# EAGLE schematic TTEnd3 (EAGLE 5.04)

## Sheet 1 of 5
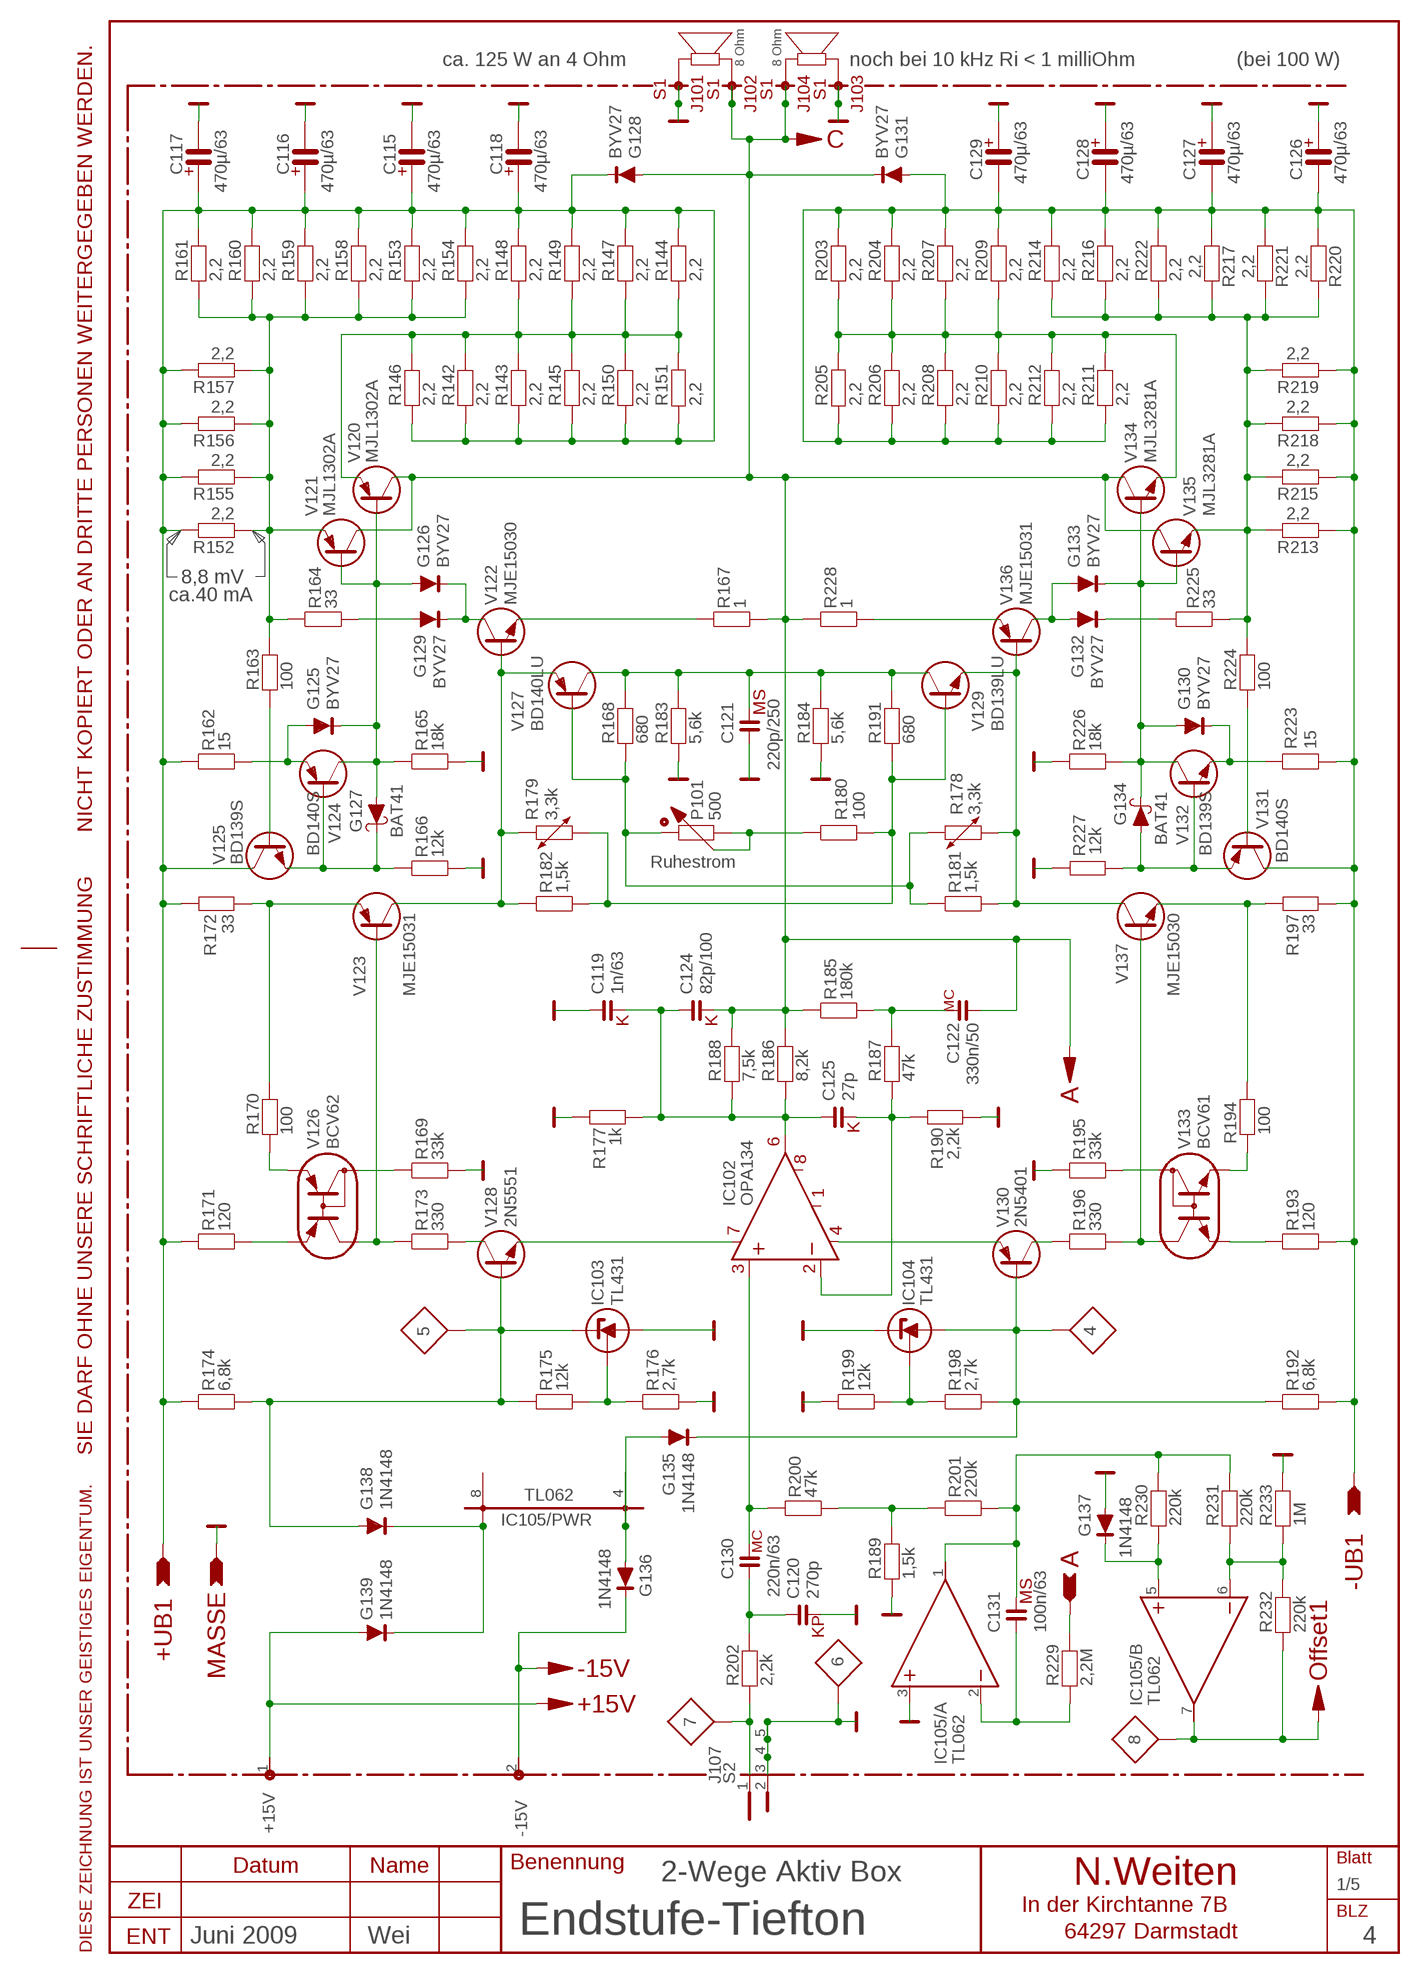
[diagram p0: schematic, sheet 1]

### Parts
C115  470µ/63  E05S12/LU  [E05S12,7U]
C116  470µ/63  E05S12/LU  [E05S12,7U]
C117  470µ/63  E05S12/LU  [E05S12,7U]
C118  470µ/63  E05S12/LU  [E05S12,7U]
C119  1n/63  K5S  [K5]
C120  270p  KP5/7/S  [KP5/7]
C121  220p/250  M05S4,5/L  [M05T4,5]
C122  330n/50  M05C4,5/S  [M05T4,5]
C124  82p/100  K5S  [K5]
C125  27p  K5S  [K5]
C126  470µ/63  E05S12/LU  [E05S12,7U]
C127  470µ/63  E05S12/LU  [E05S12,7U]
C128  470µ/63  E05S12/LU  [E05S12,7U]
C129  470µ/63  E05S12/LU  [E05S12,7U]
C130  220n/63  M05C4,5/L  [M05T4,5]
C131  100n/63  M05S2,5/L  [M05T2,5]
G125  BYV27  BYV27/S  [SOD-57]
G126  BYV27  BYV27/S  [SOD-57]
G127  BAT41  [DIO7-5]
G128  BYV27  BYV27/S  [SOD-57]
G129  BYV27  BYV27/S  [SOD-57]
G130  BYV27  BYV27/S  [SOD-57]
G131  BYV27  BYV27/S  [SOD-57]
G132  BYV27  BYV27/S  [SOD-57]
G133  BYV27  BYV27/S  [SOD-57]
G134  BAT41  [DIO7-5]
G135  1N4148  1N4148/S  [DIO7-5]
G136  1N4148  1N4148/L  [DIO7-5]
G137  1N4148  1N4148/L  [DIO7-5]
G138  1N4148  1N4148/S  [DIO7-5]
G139  1N4148  1N4148/S  [DIO7-5]
IC102  OPA134  LM6361N  [DIL-8]
IC103  TL431  [TO-92/BC]
IC104  TL431  [TO-92/BC]
IC105  TL062  LF353  [DIL-8]
J4  BERG02SW  [BERG02SW]
J101  FLACH6,3  [FLACH6,3]
J102  FLACH6,3  [FLACH6,3]
J103  FLACH6,3  [FLACH6,3]
J104  FLACH6,3  [FLACH6,3]
J107  SMB  SMBR665  [SMBR665]
MP7  7  MESS-R/S  [MESSPU/R]
MP11  5  MESS-R/S  [MESSPU/R]
MP12  4  MESS-R/S  [MESSPU/R]
MP13  6  MESS-R/L  [MESSPU/R]
MP15  8  MESS-R/S  [MESSPU/R]
P101  500  POT6,7/S  [T82P]
R142  2,2  R0207L7,5  [R7,5]
R143  2,2  R0207L7,5  [R7,5]
R144  2,2  R0207L7,5  [R7,5]
R145  2,2  R0207L7,5  [R7,5]
R146  2,2  R0207L7,5  [R7,5]
R147  2,2  R0207L7,5  [R7,5]
R148  2,2  R0207L7,5  [R7,5]
R149  2,2  R0207L7,5  [R7,5]
R150  2,2  R0207L7,5  [R7,5]
R151  2,2  R0207L7,5  [R7,5]
R152  2,2  R0207L7,5  [R7,5]
R153  2,2  R0207L7,5  [R7,5]
R154  2,2  R0207L7,5  [R7,5]
R155  2,2  R0207L7,5  [R7,5]
R156  2,2  R0207L7,5  [R7,5]
R157  2,2  R0207L7,5  [R7,5]
R158  2,2  R0207L7,5  [R7,5]
R159  2,2  R0207L7,5  [R7,5]
R160  2,2  R0207L7,5  [R7,5]
R161  2,2  R0207L7,5  [R7,5]
R162  15  R0207S7,5  [R7,5]
R163  100  R0204LR5  [R5]
R164  33  R0207S7,5  [R7,5]
R165  18k  R0207S7,5  [R7,5]
R166  12k  R0207S7,5  [R7,5]
R167  1  R0207S7,5  [R7,5]
R168  680  R0204LR5  [R5]
R169  33k  R0204SR5  [R5]
R170  100  R0204LR5  [R5]
R171  120  R0204SR5  [R5]
R172  33  R0204SR5  [R5]
R173  330  R0204SR5  [R5]
R174  6,8k  R0207S7,5  [R7,5]
R175  12k  R0204SR5  [R5]
R176  2,7k  R0204SR5  [R5]
R177  1k  R0204SR5  [R5]
R178  3,3k  NTC5,0/SB  [NTC5,0B]
R179  3,3k  NTC5,0/SB  [NTC5,0B]
R180  100  R0204SR5  [R5]
R181  1,5k  R0204SR5  [R5]
R182  1,5k  R0204SR5  [R5]
R183  5,6k  R0207L10  [R10]
R184  5,6k  R0207L10  [R10]
R185  180k  R0204SR5  [R5]
R186  8,2k  R0204LR5  [R5]
R187  47k  R0204LR5  [R5]
R188  7,5k  R0204LR5  [R5]
R189  1,5k  R0204LR5  [R5]
R190  2,2k  R0204SR5  [R5]
R191  680  R0204LR5  [R5]
R192  6,8k  R0207S7,5  [R7,5]
R193  120  R0204SR5  [R5]
R194  100  R0204LR5  [R5]
R195  33k  R0204SR5  [R5]
R196  330  R0204SR5  [R5]
R197  33  R0204SR5  [R5]
R198  2,7k  R0204SR5  [R5]
R199  12k  R0204SR5  [R5]
R200  47k  R0204SR5  [R5]
R201  220k  R0204SR5  [R5]
R202  2,2k  R0204LR5  [R5]
R203  2,2  R0207L7,5  [R7,5]
R204  2,2  R0207L7,5  [R7,5]
R205  2,2  R0207L7,5  [R7,5]
R206  2,2  R0207L7,5  [R7,5]
R207  2,2  R0207L7,5  [R7,5]
R208  2,2  R0207L7,5  [R7,5]
R209  2,2  R0207L7,5  [R7,5]
R210  2,2  R0207L7,5  [R7,5]
R211  2,2  R0207L7,5  [R7,5]
R212  2,2  R0207L7,5  [R7,5]
R213  2,2  R0207L7,5  [R7,5]
R214  2,2  R0207L7,5  [R7,5]
R215  2,2  R0207L7,5  [R7,5]
R216  2,2  R0207L7,5  [R7,5]
R217  2,2  R0207L7,5  [R7,5]
R218  2,2  R0207L7,5  [R7,5]
R219  2,2  R0207L7,5  [R7,5]
R220  2,2  R0207L7,5  [R7,5]
R221  2,2  R0207L7,5  [R7,5]
R222  2,2  R0207L7,5  [R7,5]
R223  15  R0207S7,5  [R7,5]
R224  100  R0204LR5  [R5]
R225  33  R0207S7,5  [R7,5]
R226  18k  R0207S7,5  [R7,5]
R227  12k  R0207S7,5  [R7,5]
R228  1  R0207S7,5  [R7,5]
R229  2,2M  R0204LR5  [R5]
R230  220k  R0204LR5  [R5]
R231  220k  R0204LR5  [R5]
R232  220k  R0204LR5  [R5]
R233  1M  R0204LR5  [R5]
V120  MJL1302A  MJL1302ALU  [TO-264/LU]
V121  MJL1302A  MJL1302ALU  [TO-264/LU]
V122  MJE15030  MJE15030LU  [TO-220/LU]
V123  MJE15031  MJE15031LU  [TO-220/LU]
V124  BD140S  [TO-126/S]
V125  BD139S  [TO-126/S]
V126  BCV62  [SOT143]
V127  BD140LU  [TO-126/LU]
V128  2N5551  [TO-92]
V129  BD139LU  [TO-126/LU]
V130  2N5401  [TO-92]
V131  BD140S  [TO-126/S]
V132  BD139S  [TO-126/S]
V133  BCV61  [SOT143]
V134  MJL3281A  MJL3281ALU  [TO-264/LU]
V135  MJL3281A  MJL3281ALU  [TO-264/LU]
V136  MJE15031  MJE15031LU  [TO-220/LU]
V137  MJE15030  MJE15030LU  [TO-220/LU]

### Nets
+UB1: C115.1 C116.1 C117.1 C118.1 G128.2(K) R142.1 R143.1 R144.2 R145.1 R146.1 R147.2 R148.2 R149.2 R150.1 R151.2 R152.2 R153.2 R154.2 R155.2 R156.2 R157.2 R158.2 R159.2 R160.2 R161.2 R162.1 R171.1 R172.1 R174.1 V125.2(C) ; also sheet 3
-UB1: C126.2 C127.2 C128.2 C129.2 G131.1(A) R192.2 R193.2 R197.2 R203.2 R204.2 R205.2 R206.1 R207.2 R208.1 R209.2 R210.1 R211.1 R212.1 R213.2 R214.2 R215.2 R216.2 R217.2 R218.2 R219.2 R220.2 R221.2 R222.2 R223.2 V131.2(C) ; also sheet 3
MASSE: C115.2 C116.2 C117.2 C118.2 C119.1 C120.2 C121.1 C126.1 C127.1 C128.1 C129.1 G137.1(A) IC103.2(A) IC104.3(K) IC105.3(/A:+IN) J101.1 J101.2 J103.1 J103.2 J107.2(MASSE) J107.3(MASSE) J107.4(MASSE) J107.5(MASSE) MP13.1 R165.2 R166.2 R169.2 R176.2 R177.1 R183.1 R184.1 R189.1 R190.2 R195.1 R199.1 R226.1 R227.1 R233.2 ; also sheet 2,3,4
N$1: C120.1 C130.1 R202.2
N$2: C130.2 IC102.3(+IN) R200.1
N$3: IC103.1(R) R175.2 R176.1
N$4: G138.1(A) IC103.3(K) MP11.1 R174.2 R175.1 V128.2(B)
N$5: IC102.7(V+) V128.1(E)
N$6: IC104.1(R) R198.1 R199.2
N$7: G135.2(K) IC104.2(A) MP12.1 R192.1 R198.2 V130.2(B)
N$8: IC102.4(V-) V130.1(E)
N$9: C119.2 C124.1 C125.1 IC102.6(OUT) R177.2 R186.1 R188.1
N$10: C125.2 IC102.2(-IN) R187.1 R190.1
N$11: C122.2 R185.2 R187.2
N$13: R173.2 V128.3(C)
N$14: R196.1 V130.3(C)
N$15: R170.2 R172.2 V123.3(E)
N$16: C121.2 R168.2 R183.2 R184.2 R191.2 V127.2(C) V129.2(C)
N$17: R171.2 V126.3(E1)
N$18: R178.2 R181.2 V129.1(E) V136.1(B) V137.2(C)
N$19: R173.1 V123.1(B) V126.2(C1)
N$20: R169.1 V126.1(B1B2C2)
N$21: R170.1 V126.4(E2)
N$22: R193.1 V133.3(E1)
N$23: G125.2(K) G126.1(A) G127.1(A) R165.1 V120.1(B) V121.1(B) V124.2(C)
N$24: G125.1(A) R162.2 V124.1(E)
N$25: J107.1 MP7.1 R202.1
N$26: R152.1 R153.1 R154.1 R155.1 R156.1 R157.1 R158.1 R159.1 R160.1 R161.1 R163.2 R164.1 V121.3(E)
N$27: R196.2 V133.2(C1) V137.1(B)
N$28: R195.2 V133.1(B1B2C2)
N$30: R194.1 V133.4(E2)
N$31: R194.2 R197.1 V137.3(E)
N$32: R163.1 V125.3(B)
N$33: G127.2(K) R166.1 V124.3(B) V125.1(E)
N$35: R213.1 R214.1 R215.1 R216.1 R217.1 R218.1 R219.1 R220.1 R221.1 R222.1 R224.2 R225.2 V135.3(E)
N$36: G130.2(K) R223.1 V132.1(E)
N$37: G130.1(A) G133.2(K) G134.2(K) R226.2 V132.2(C) V134.1(B) V135.1(B)
N$38: G132.1(A) G133.1(A) V136.2(C)
N$39: G132.2(K) R225.1
N$40: R224.1 V131.3(B)
N$41: G134.1(A) R227.2 V131.1(E) V132.3(B)
N$42: R167.1 V122.3(E)
N$43: C131.2 IC105.1(/A:OUT) R201.2 R230.2 R231.2
N$44: C131.1 IC105.2(/A:-IN) R229.1
N$45: G137.2(K) IC105.5(/B:+IN) R230.1
N$46: IC105.6(/B:-IN) R231.1 R232.2 R233.1
N$47: G135.1(A) G136.1(A) IC105.4(/PWR:VEE)
N$50: R142.2 R143.2 R144.1 R145.2 R146.2 R147.1 R148.1 R149.1 R150.2 R151.1 V120.3(E)
N$51: R203.1 R204.1 R205.1 R206.2 R207.1 R208.2 R209.1 R210.2 R211.2 R212.2 V134.3(E)
N$52: C122.1 C124.2 G128.1(A) G131.2(K) J102.1 J102.2 J104.1 J104.2 R167.2 R185.1 R186.2 R188.2 R228.1 R229.2 V120.2(C) V121.2(C) V134.2(C) V135.2(C) ; also sheet 3
N$93: R189.2 R200.2 R201.1
N$98: G136.2(K) J4.2 ; also sheet 2
N$187: R179.1 R182.1 V122.1(B) V123.2(C) V127.1(E)
N$204: P101.1 R168.1 R178.1 R181.1 V127.3(B)
N$205: R179.2 R180.2 R182.2 R191.1 V129.3(B)
N$214: G138.2(K) G139.2(K) IC105.8(/PWR:VCC)
N$215: G139.1(A) J4.1 ; also sheet 2
N$218: P101.2 P101.S R180.1
N$219: R228.2 V136.3(E)
N$220: G126.2(K) G129.2(K) V122.2(C)
N$221: G129.1(A) R164.2
OFFSET1: IC105.7(/B:OUT) MP15.1 R232.1 ; also sheet 3
Unconnected: IC102.1(BAL1) IC102.8(BAL2)

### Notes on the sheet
- ca. 125 W an 4 Ohm | 8 Ohm | 8 Ohm | noch bei 10 kHz Ri < 1 milliOhm | (bei 100 W)
- 8,8 mV
- ca.40 mA
- Ruhestrom
- +15V | -15V
- 2-Wege Aktiv Box
- Endstufe-Tiefton
- Juni 2009 | Wei | 4

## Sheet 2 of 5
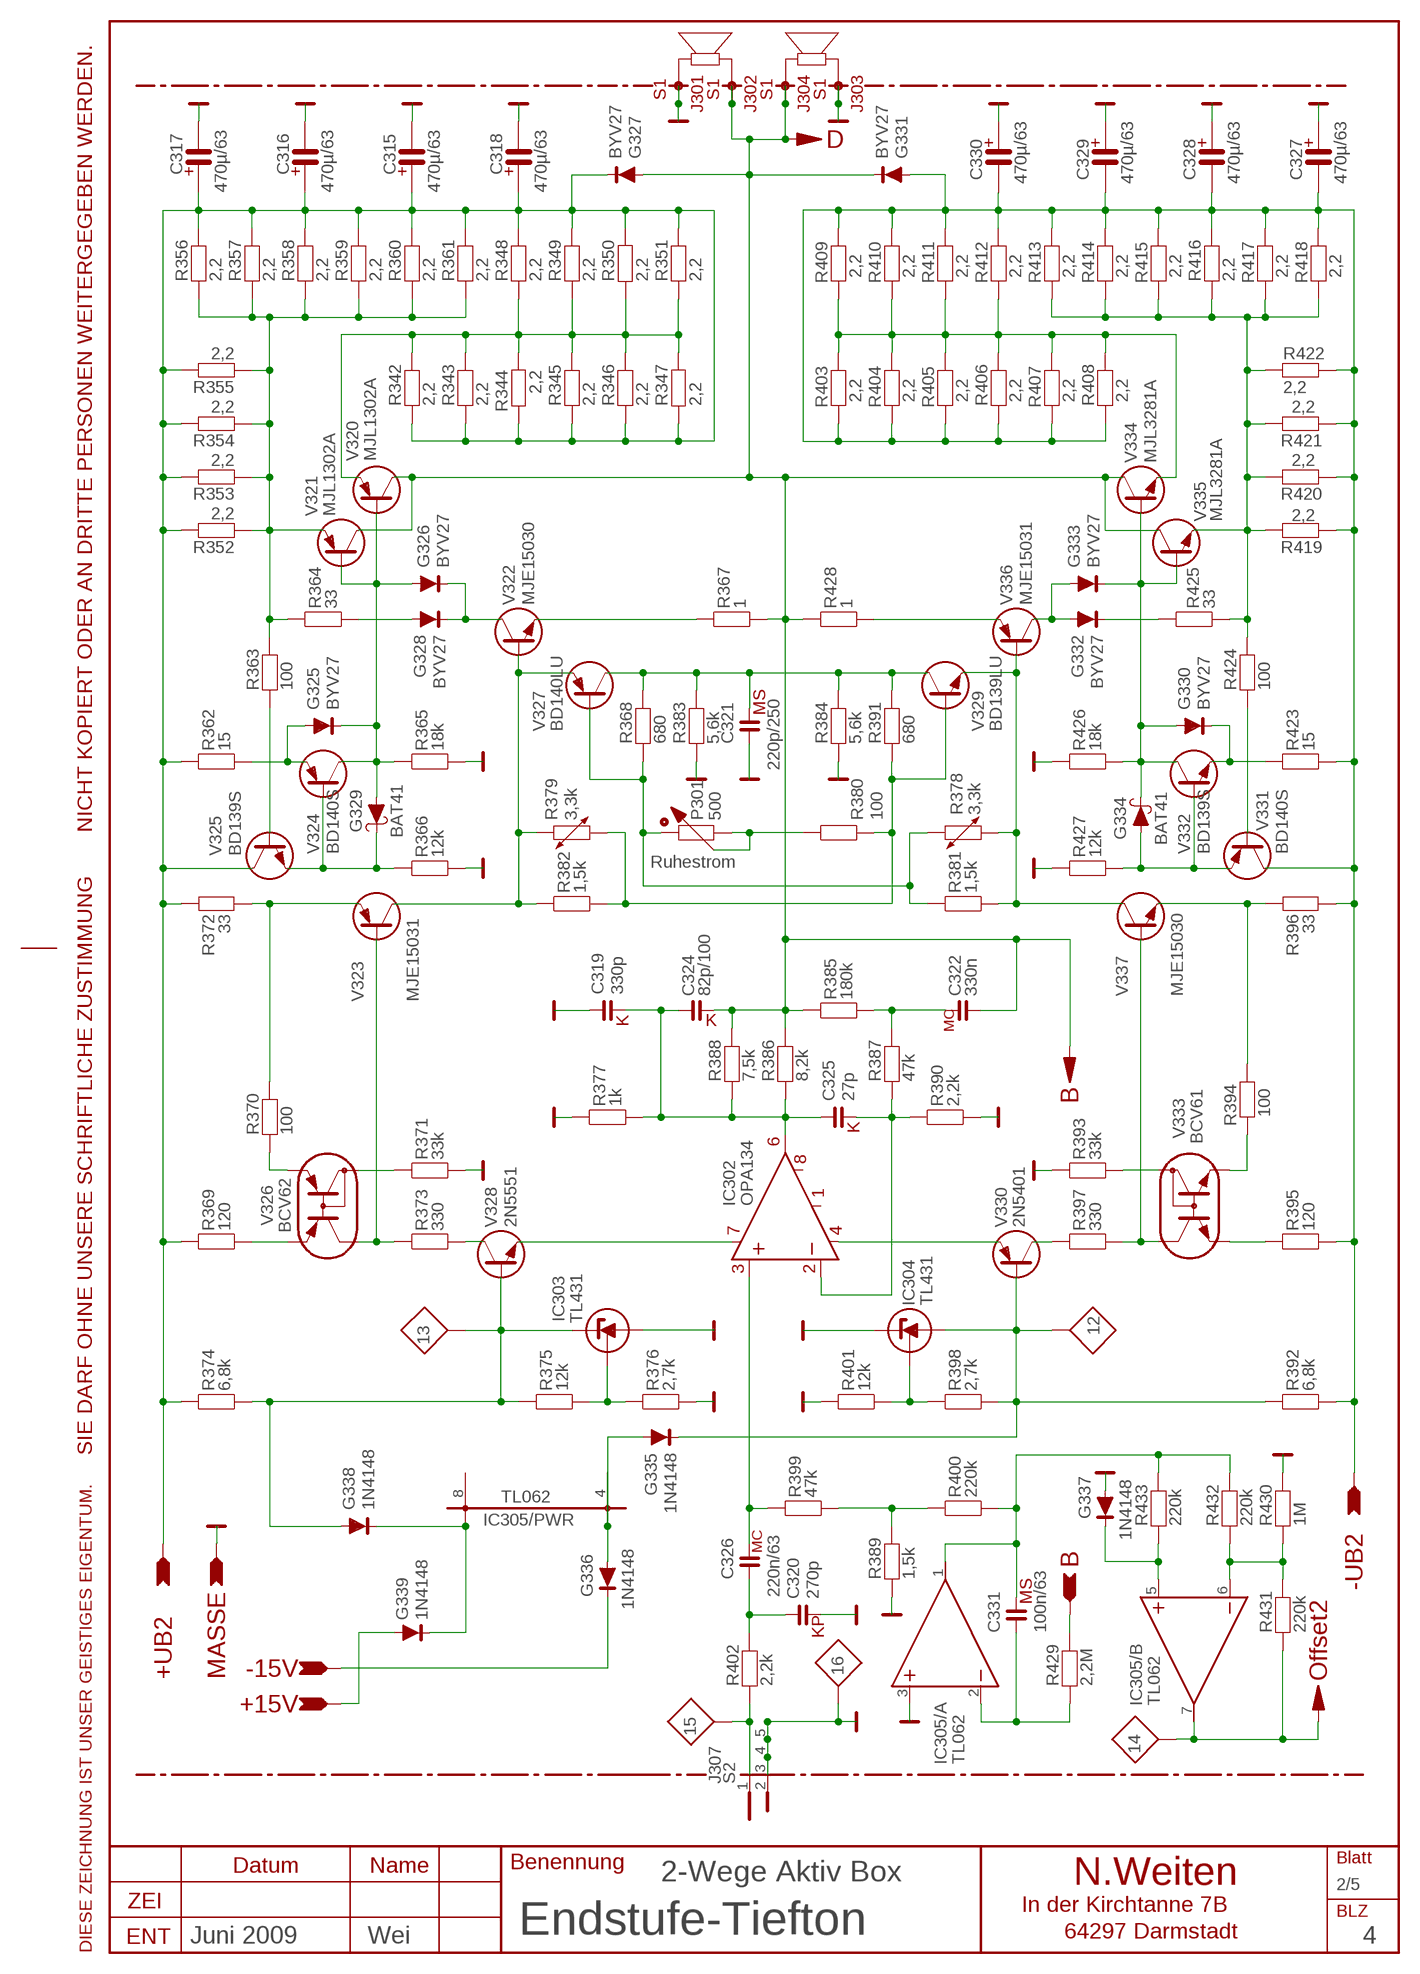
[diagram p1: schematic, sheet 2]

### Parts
C315  470µ/63  E05S12/LU  [E05S12,7U]
C316  470µ/63  E05S12/LU  [E05S12,7U]
C317  470µ/63  E05S12/LU  [E05S12,7U]
C318  470µ/63  E05S12/LU  [E05S12,7U]
C319  330p  K5S  [K5]
C320  270p  KP5/7/S  [KP5/7]
C321  220p/250  M05S4,5/L  [M05T4,5]
C322  330n  M05C4,5/S  [M05T4,5]
C324  82p/100  K5L  [K5]
C325  27p  K5S  [K5]
C326  220n/63  M05C4,5/L  [M05T4,5]
C327  470µ/63  E05S12/LU  [E05S12,7U]
C328  470µ/63  E05S12/LU  [E05S12,7U]
C329  470µ/63  E05S12/LU  [E05S12,7U]
C330  470µ/63  E05S12/LU  [E05S12,7U]
C331  100n/63  M05S2,5/L  [M05T2,5]
G325  BYV27  BYV27/S  [SOD-57]
G326  BYV27  BYV27/S  [SOD-57]
G327  BYV27  BYV27/S  [SOD-57]
G328  BYV27  BYV27/S  [SOD-57]
G329  BAT41  [DIO7-5]
G330  BYV27  BYV27/S  [SOD-57]
G331  BYV27  BYV27/S  [SOD-57]
G332  BYV27  BYV27/S  [SOD-57]
G333  BYV27  BYV27/S  [SOD-57]
G334  BAT41  [DIO7-5]
G335  1N4148  1N4148/S  [DIO7-5]
G336  1N4148  1N4148/L  [DIO7-5]
G337  1N4148  1N4148/L  [DIO7-5]
G338  1N4148  1N4148/S  [DIO7-5]
G339  1N4148  1N4148/S  [DIO7-5]
IC302  OPA134  LM6361N  [DIL-8]
IC303  TL431  [TO-92/BC]
IC304  TL431  [TO-92/BC]
IC305  TL062  LF353  [DIL-8]
J301  FLACH6,3  [FLACH6,3]
J302  FLACH6,3  [FLACH6,3]
J303  FLACH6,3  [FLACH6,3]
J304  FLACH6,3  [FLACH6,3]
J307  SMB  SMBR665  [SMBR665]
MP8  15  MESS-R/S  [MESSPU/R]
MP9  13  MESS-R/S  [MESSPU/R]
MP10  12  MESS-R/S  [MESSPU/R]
MP14  16  MESS-R/L  [MESSPU/R]
MP16  14  MESS-R/S  [MESSPU/R]
P301  500  POT6,7/S  [T82P]
R342  2,2  R0207L7,5  [R7,5]
R343  2,2  R0207L7,5  [R7,5]
R344  2,2  R0207L7,5  [R7,5]
R345  2,2  R0207L7,5  [R7,5]
R346  2,2  R0207L7,5  [R7,5]
R347  2,2  R0207L7,5  [R7,5]
R348  2,2  R0207L7,5  [R7,5]
R349  2,2  R0207L7,5  [R7,5]
R350  2,2  R0207L7,5  [R7,5]
R351  2,2  R0207L7,5  [R7,5]
R352  2,2  R0207L7,5  [R7,5]
R353  2,2  R0207L7,5  [R7,5]
R354  2,2  R0207L7,5  [R7,5]
R355  2,2  R0207L7,5  [R7,5]
R356  2,2  R0207L7,5  [R7,5]
R357  2,2  R0207L7,5  [R7,5]
R358  2,2  R0207L7,5  [R7,5]
R359  2,2  R0207L7,5  [R7,5]
R360  2,2  R0207L7,5  [R7,5]
R361  2,2  R0207L7,5  [R7,5]
R362  15  R0207S7,5  [R7,5]
R363  100  R0204LR5  [R5]
R364  33  R0207S7,5  [R7,5]
R365  18k  R0207S7,5  [R7,5]
R366  12k  R0207S7,5  [R7,5]
R367  1  R0207S7,5  [R7,5]
R368  680  R0204LR5  [R5]
R369  120  R0204SR5  [R5]
R370  100  R0204LR5  [R5]
R371  33k  R0204SR5  [R5]
R372  33  R0204SR5  [R5]
R373  330  R0204SR5  [R5]
R374  6,8k  R0207S7,5  [R7,5]
R375  12k  R0204SR5  [R5]
R376  2,7k  R0204SR5  [R5]
R377  1k  R0204SR5  [R5]
R378  3,3k  NTC5,0/SB  [NTC5,0B]
R379  3,3k  NTC5,0/SB  [NTC5,0B]
R380  100  R0204SR5  [R5]
R381  1,5k  R0204SR5  [R5]
R382  1,5k  R0204SR5  [R5]
R383  5,6k  R0207L10  [R10]
R384  5,6k  R0207L10  [R10]
R385  180k  R0204SR5  [R5]
R386  8,2k  R0204LR5  [R5]
R387  47k  R0204LR5  [R5]
R388  7,5k  R0204LR5  [R5]
R389  1,5k  R0204LR5  [R5]
R390  2,2k  R0204SR5  [R5]
R391  680  R0204LR5  [R5]
R392  6,8k  R0207S7,5  [R7,5]
R393  33k  R0204SR5  [R5]
R394  100  R0204LR5  [R5]
R395  120  R0204SR5  [R5]
R396  33  R0204SR5  [R5]
R397  330  R0204SR5  [R5]
R398  2,7k  R0204SR5  [R5]
R399  47k  R0204SR5  [R5]
R400  220k  R0204SR5  [R5]
R401  12k  R0204SR5  [R5]
R402  2,2k  R0204LR5  [R5]
R403  2,2  R0207L7,5  [R7,5]
R404  2,2  R0207L7,5  [R7,5]
R405  2,2  R0207L7,5  [R7,5]
R406  2,2  R0207L7,5  [R7,5]
R407  2,2  R0207L7,5  [R7,5]
R408  2,2  R0207L7,5  [R7,5]
R409  2,2  R0207L7,5  [R7,5]
R410  2,2  R0207L7,5  [R7,5]
R411  2,2  R0207L7,5  [R7,5]
R412  2,2  R0207L7,5  [R7,5]
R413  2,2  R0207L7,5  [R7,5]
R414  2,2  R0207L7,5  [R7,5]
R415  2,2  R0207L7,5  [R7,5]
R416  2,2  R0207L7,5  [R7,5]
R417  2,2  R0207L7,5  [R7,5]
R418  2,2  R0207L7,5  [R7,5]
R419  2,2  R0207L7,5  [R7,5]
R420  2,2  R0207L7,5  [R7,5]
R421  2,2  R0207L7,5  [R7,5]
R422  2,2  R0207L7,5  [R7,5]
R423  15  R0207S7,5  [R7,5]
R424  100  R0204LR5  [R5]
R425  33  R0207S7,5  [R7,5]
R426  18k  R0207S7,5  [R7,5]
R427  12k  R0207S7,5  [R7,5]
R428  1  R0207S7,5  [R7,5]
R429  2,2M  R0204LR5  [R5]
R430  1M  R0204LR5  [R5]
R431  220k  R0204LR5  [R5]
R432  220k  R0204LR5  [R5]
R433  220k  R0204LR5  [R5]
V320  MJL1302A  MJL1302ALU  [TO-264/LU]
V321  MJL1302A  MJL1302ALU  [TO-264/LU]
V322  MJE15030  MJE15030LU  [TO-220/LU]
V323  MJE15031  MJE15031LU  [TO-220/LU]
V324  BD140S  [TO-126/S]
V325  BD139S  [TO-126/S]
V326  BCV62  [SOT143]
V327  BD140LU  [TO-126/LU]
V328  2N5551  [TO-92]
V329  BD139LU  [TO-126/LU]
V330  2N5401  [TO-92]
V331  BD140S  [TO-126/S]
V332  BD139S  [TO-126/S]
V333  BCV61  [SOT143]
V334  MJL3281A  MJL3281ALU  [TO-264/LU]
V335  MJL3281A  MJL3281ALU  [TO-264/LU]
V336  MJE15031  MJE15031LU  [TO-220/LU]
V337  MJE15030  MJE15030LU  [TO-220/LU]

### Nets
+UB2: C315.1 C316.1 C317.1 C318.1 G327.2(K) R342.1 R343.1 R344.2 R345.1 R346.1 R347.2 R348.2 R349.2 R350.1 R351.2 R352.2 R353.2 R354.2 R355.2 R356.2 R357.2 R358.2 R359.2 R360.2 R361.2 R362.1 R369.1 R372.1 R374.1 V325.2(C) ; also sheet 4
-UB2: C327.2 C328.2 C329.2 C330.2 G331.1(A) R392.2 R395.2 R396.2 R403.2 R404.2 R405.2 R406.1 R407.2 R408.1 R409.2 R410.1 R411.1 R412.1 R413.2 R414.2 R415.2 R416.2 R417.2 R418.2 R419.2 R420.2 R421.2 R422.2 R423.2 V331.2(C) ; also sheet 4
MASSE: C315.2 C316.2 C317.2 C318.2 C319.1 C320.2 C321.1 C327.1 C328.1 C329.1 C330.1 G337.1(A) IC303.2(A) IC304.3(K) IC305.3(/A:+IN) J301.1 J301.2 J303.1 J303.2 J307.2(MASSE) J307.3(MASSE) J307.4(MASSE) J307.5(MASSE) MP14.1 R365.2 R366.2 R371.2 R376.2 R377.1 R383.1 R384.1 R389.1 R390.2 R393.1 R401.1 R426.1 R427.1 R430.2 ; also sheet 1,3,4
N$54: C326.2 IC302.3(+IN) R399.1
N$55: IC303.1(R) R375.2 R376.1
N$56: G338.1(A) IC303.3(K) MP9.1 R374.2 R375.1 V328.2(B)
N$58: IC304.1(R) R398.1 R401.2
N$59: IC302.4(V-) V330.1(E)
N$60: C319.2 C324.1 C325.1 IC302.6(OUT) R377.2 R386.1 R388.1
N$61: C325.2 IC302.2(-IN) R387.1 R390.1
N$62: C322.2 R385.2 R387.2
N$63: R373.2 V328.3(C)
N$64: R397.1 V330.3(C)
N$65: R370.2 R372.2 V323.3(E)
N$66: R379.1 R382.1 V322.1(B) V323.2(C) V327.1(E)
N$67: R369.2 V326.3(E1)
N$68: R373.1 V323.1(B) V326.2(C1)
N$69: R371.1 V326.1(B1B2C2)
N$70: R370.1 V326.4(E2)
N$72: IC302.7(V+) V328.1(E)
N$73: G325.1(A) R362.2 V324.1(E)
N$74: R352.1 R353.1 R354.1 R355.1 R356.1 R357.1 R358.1 R359.1 R360.1 R361.1 R363.2 R364.1 V321.3(E)
N$75: R397.2 V333.2(C1) V337.1(B)
N$76: R393.2 V333.1(B1B2C2)
N$77: R395.1 V333.3(E1)
N$78: R394.1 V333.4(E2)
N$79: R394.2 R396.1 V337.3(E)
N$80: R378.2 R381.2 V329.1(E) V336.1(B) V337.2(C)
N$82: R413.1 R414.1 R415.1 R416.1 R417.1 R418.1 R419.1 R420.1 R421.1 R422.1 R424.2 R425.2 V335.3(E)
N$83: G330.2(K) R423.1 V332.1(E)
N$84: G330.1(A) G333.2(K) G334.2(K) R426.2 V332.2(C) V334.1(B) V335.1(B)
N$85: J307.1 MP8.1 R402.1
N$86: R363.1 V325.3(B)
N$87: P301.1 R368.1 R378.1 R381.1 V327.3(B)
N$88: R379.2 R380.2 R382.2 R391.1 V329.3(B)
N$89: G335.2(K) IC304.2(A) MP10.1 R392.1 R398.2 V330.2(B)
N$90: C321.2 R368.2 R383.2 R384.2 R391.2 V327.2(C) V329.2(C)
N$91: G329.2(K) R366.1 V324.3(B) V325.1(E)
N$92: G328.1(A) R364.2
N$94: C331.2 IC305.1(/A:OUT) R400.2 R432.2 R433.2
N$95: C331.1 IC305.2(/A:-IN) R429.1
N$96: G337.2(K) IC305.5(/B:+IN) R433.1
N$97: IC305.6(/B:-IN) R430.1 R431.2 R432.1
N$98: G336.2(K) ; also sheet 1
N$101: R342.2 R343.2 R344.1 R345.2 R346.2 R347.1 R348.1 R349.1 R350.2 R351.1 V320.3(E)
N$102: R403.1 R404.1 R405.1 R406.2 R407.1 R408.2 R409.1 R410.2 R411.2 R412.2 V334.3(E)
N$103: C322.1 C324.2 G327.1(A) G331.2(K) J302.1 J302.2 J304.1 J304.2 R367.2 R385.1 R386.2 R388.2 R428.1 R429.2 V320.2(C) V321.2(C) V334.2(C) V335.2(C) ; also sheet 4
N$107: G325.2(K) G326.1(A) G329.1(A) R365.1 V320.1(B) V321.1(B) V324.2(C)
N$108: C320.1 C326.1 R402.2
N$155: G335.1(A) G336.1(A) IC305.4(/PWR:VEE)
N$179: P301.2 P301.S R380.1
N$181: G326.2(K) G328.2(K) V322.2(C)
N$185: R389.2 R399.2 R400.1
N$215: G339.1(A) ; also sheet 1
N$216: G338.2(K) G339.2(K) IC305.8(/PWR:VCC)
N$224: R367.1 V322.3(E)
N$225: G332.2(K) R425.1
N$226: G332.1(A) G333.1(A) V336.2(C)
N$227: R424.1 V331.3(B)
N$228: G334.1(A) R427.2 V331.1(E) V332.3(B)
N$229: R428.2 V336.3(E)
OFFSET2: IC305.7(/B:OUT) MP16.1 R431.1 ; also sheet 4
Unconnected: IC302.1(BAL1) IC302.8(BAL2)

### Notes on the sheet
- Ruhestrom
- 2-Wege Aktiv Box
- Endstufe-Tiefton
- Juni 2009 | Wei | 4

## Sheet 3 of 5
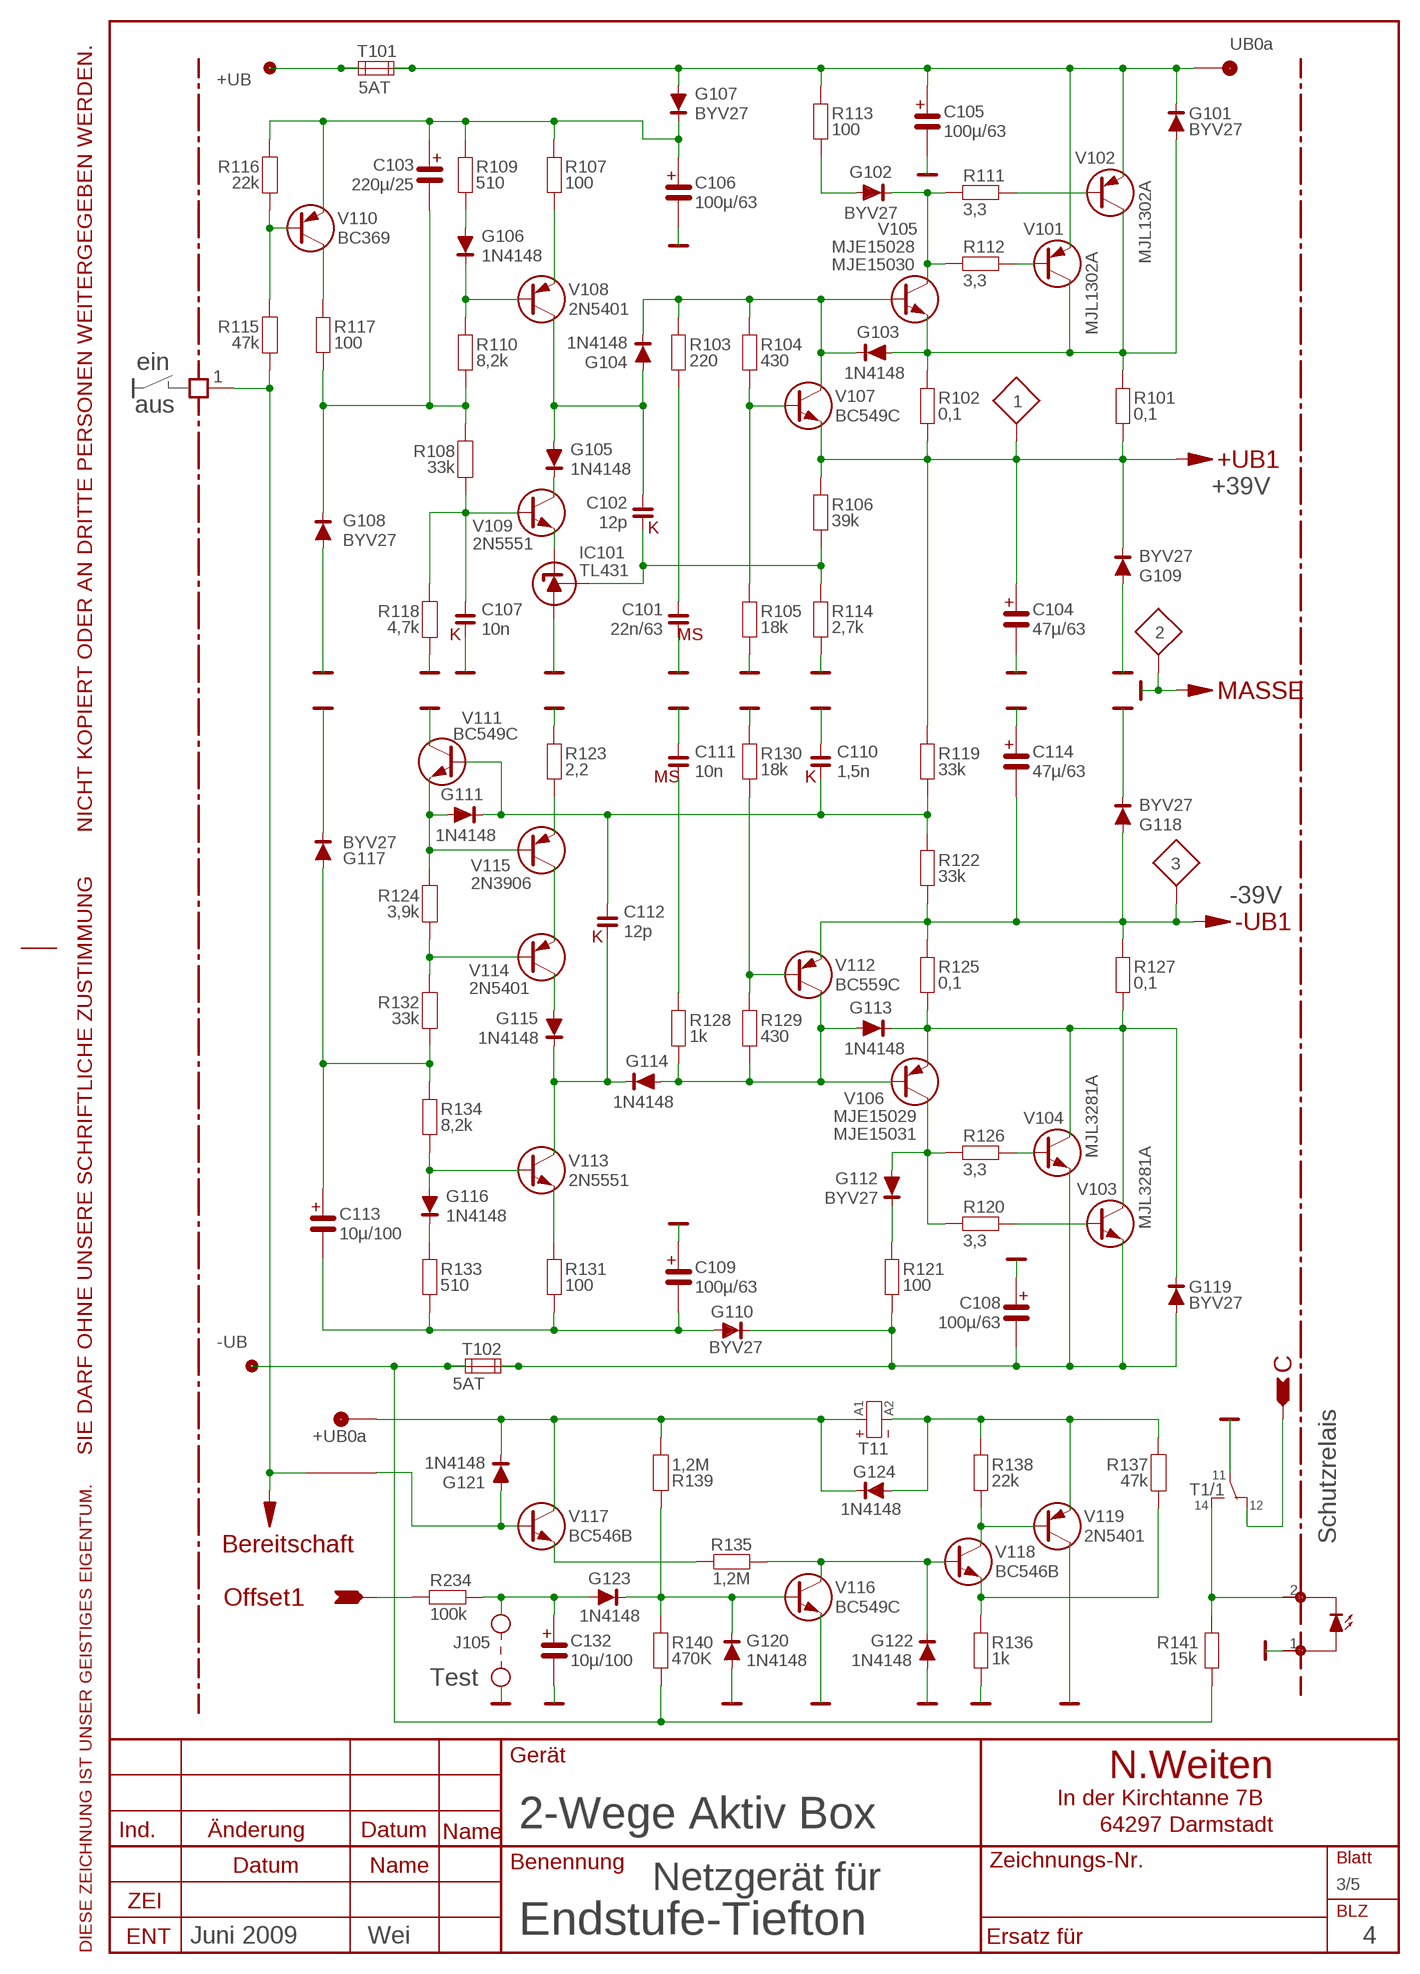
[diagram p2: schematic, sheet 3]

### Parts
C101  22n/63  M05S2,5/S  [M05T2,5]
C102  12p  K5S  [K5]
C103  220µ/25  E3,5S08/S  [E3,5S08]
C104  47µ/63  E3,5S08/S  [E3,5S08]
C105  100µ/63  E05S10/S  [E05S10,5]
C106  100µ/63  E05S10/S  [E05S10,5]
C107  10n  K5S  [K5]
C108  100µ/63  E05S10/S  [E05S10,5]
C109  100µ/63  E05S10/S  [E05S10,5]
C110  1,5n  K5S  [K5]
C111  10n  M05S2,5/S  [M05T2,5]
C112  12p  K5S  [K5]
C113  10µ/100  E2,0S05/S  [E2,0S05]
C114  47µ/63  E2,5S08/S  [E2,5S08]
C132  10µ/100  E2,0S05/S  [E2,0S05]
EIN1  1  LÖTFA  [LÖTFA]
G101  BYV27  BYV27/S  [SOD-57]
G102  BYV27  BYV27/L  [SOD-57]
G103  1N4148  1N4148/L  [DIO7-5]
G104  1N4148  1N4148/S  [DIO7-5]
G105  1N4148  1N4148/S  [DIO7-5]
G106  1N4148  1N4148/S  [DIO7-5]
G107  BYV27  BYV27/S  [SOD-57]
G108  BYV27  BYV27/S  [SOD-57]
G109  BYV27  BYV27/S  [SOD-57]
G110  BYV27  BYV27/S  [SOD-57]
G111  1N4148  1N4148/L  [DIO7-5]
G112  BYV27  BYV27/L  [SOD-57]
G113  1N4148  1N4148/L  [DIO7-5]
G114  1N4148  1N4148/L  [DIO7-5]
G115  1N4148  1N4148/S  [DIO7-5]
G116  1N4148  1N4148/S  [DIO7-5]
G117  BYV27  BYV27/S  [SOD-57]
G118  BYV27  BYV27/S  [SOD-57]
G119  BYV27  BYV27/S  [SOD-57]
G120  1N4148  1N4148/S  [DIO7-5]
G121  1N4148  1N4148/S  [DIO7-5]
G122  1N4148  1N4148/S  [DIO7-5]
G123  1N4148  1N4148/S  [DIO7-5]
G124  1N4148  1N4148/S  [DIO7-5]
IC101  TL431  [TO-92/BC]
J105  BERG02SG  JUMP/O/S  [BERG02SG]
J106  BERG02SW  [BERG02SW]
MP1  1  MESS-R/S  [MESSPU/R]
MP2  3  MESS-R/S  [MESSPU/R]
MP3  2  MESS-R/S  [MESSPU/R]
R101  0,1  R25X6,5/S  [R27,5]
R102  0,1  R25X6,5/S  [R27,5]
R103  220  R0204SR5  [R5]
R104  430  R0204SR5  [R5]
R105  18k  R0204SR5  [R5]
R106  39k  R0204SR5  [R5]
R107  100  R0204SR5  [R5]
R108  33k  R0204SR5  [R5]
R109  510  R0204SR5  [R5]
R110  8,2k  R0204SR5  [R5]
R111  3,3  R0207L7,5  [R7,5]
R112  3,3  R0207L7,5  [R7,5]
R113  100  R0207S7,5  [R7,5]
R114  2,7k  R0204SR5  [R5]
R115  47k  R0204SR5  [R5]
R116  22k  R0204SR5  [R5]
R117  100  R0204SR5  [R5]
R118  4,7k  R0204SR5  [R5]
R119  33k  R0207S7,5  [R7,5]
R120  3,3  R0207L7,5  [R7,5]
R121  100  R0207S7,5  [R7,5]
R122  33k  R0204SR5  [R5]
R123  2,2  R0204SR5  [R5]
R124  3,9k  R0204SR5  [R5]
R125  0,1  R25X6,5/S  [R27,5]
R126  3,3  R0207L7,5  [R7,5]
R127  0,1  R25X6,5/S  [R27,5]
R128  1k  R0204SR5  [R5]
R129  430  R0204SR5  [R5]
R130  18k  R0204SR5  [R5]
R131  100  R0204SR5  [R5]
R132  33k  R0204SR5  [R5]
R133  510  R0204SR5  [R5]
R134  8,2k  R0204SR5  [R5]
R135  1,2M  R0204SR5  [R5]
R136  1k  R0204SR5  [R5]
R137  47k  R0204SR5  [R5]
R138  22k  R0204SR5  [R5]
R139  1,2M  R0204LR5  [R5]
R140  470K  R0204SR5  [R5]
R141  15k  R0207S7,5  [R7,5]
R234  100k  R0204LR5  [R5]
T1  TYCORT314  [TYCORT314]
T101  5AT  SI520/L  [SICH5*20]
T102  5AT  SI520/L  [SICH5*20]
V101  MJL1302A  MJL1302ALU  [TO-264/LU]
V102  MJL1302A  MJL1302ALU  [TO-264/LU]
V103  MJL3281A  MJL3281ALU  [TO-264/LU]
V104  MJL3281A  MJL3281ALU  [TO-264/LU]
V105  MJE15028  MJE15030LU  [TO-220/LU]
V106  MJE15029  MJE15031LU  [TO-220/LU]
V107  BC549C  [TO-92/BC]
V108  2N5401  [TO-92]
V109  2N5551  [TO-92]
V110  BC369  BC640  [SOT-54]
V111  BC549C  [TO-92/BC]
V112  BC559C  [TO-92/BC]
V113  2N5551  [TO-92]
V114  2N5401  [TO-92]
V115  2N3906  [TO-92]
V116  BC549C  [TO-92/BC]
V117  BC546B  BC547C  [TO-92/BC]
V118  BC546B  BC547C  [TO-92/BC]
V119  2N5401  [TO-92]

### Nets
+UB: T101.1 T101.2 ; also sheet 4
+UB1: C104.1 G109.2(K) MP1.1 R101.2 R102.2 R106.1 R119.1 V107.3(E) ; also sheet 1
-UB: R140.2 R141.1 T102.1 T102.2 ; also sheet 4
-UB0: C108.2 G110.2(K) G119.1(A) R121.2 T102.3 T102.4 V103.3(E) V104.3(E)
-UB1: C114.2 G118.1(A) MP2.1 R122.2 R125.1 R127.1 V112.3(E) ; also sheet 1
MASSE: C101.2 C104.2 C105.2 C106.2 C107.2 C108.1 C109.1 C110.1 C111.1 C114.1 C132.2 G108.1(A) G109.1(A) G117.2(K) G118.2(K) G120.1(A) G122.1(A) IC101.2(A) J105.2 J106.1 MP3.1 R105.2 R114.2 R118.2 R123.1 R130.1 R136.2 T1.11 V111.1(C) V116.3(E) V119.3(C) ; also sheet 1,2,4
N$52: T1.12 ; also sheet 1
N$57: R138.2 V118.1(C) V119.2(B)
N$81: R136.1 R137.2 V118.3(E)
N$104: C132.1 G123.1(A) J105.1 R234.2
N$142: G121.2(K) G124.2(K) R139.2 T1.A1(1:A1) V117.1(C)
N$143: G106.1(A) R109.2
N$144: G106.2(K) R110.1 V108.2(B)
N$145: R107.2 V108.1(E)
N$146: C103.2 G108.2(K) R108.1 R110.2 R117.2
N$147: C107.1 R108.2 R118.1 V109.2(B)
N$148: G103.2(K) G104.2(K) R103.1 R104.1 V105.1(B) V107.1(C)
N$149: IC101.3(K) V109.1(E)
N$150: G102.2(K) R111.1 R112.1 V105.2(C)
N$151: G101.1(A) G103.1(A) R101.1 R102.1 V101.2(C) V102.2(C) V105.3(E)
N$152: R104.2 R105.1 V107.2(B)
N$154: C102.2 IC101.1(R) R106.2 R114.1
N$157: R123.2 V115.1(E)
N$158: G111.1(A) R124.1 V111.3(E) V115.2(B)
N$159: V114.1(E) V115.3(C)
N$160: R124.2 R132.1 V114.2(B)
N$161: C110.2 C112.1 G111.2(K) R119.2 R122.1 V111.2(B)
N$162: R129.1 R130.2 V112.2(B)
N$163: G113.1(A) G114.1(A) R128.2 R129.2 V106.1(B) V112.1(C)
N$164: G113.2(K) G119.2(K) R125.2 R127.2 V103.2(C) V104.2(C) V106.3(E)
N$165: G112.1(A) R120.1 R126.1 V106.2(C)
N$166: R131.1 V113.1(E)
N$167: G116.2(K) R133.1
N$168: G116.1(A) R134.2 V113.2(B)
N$169: C113.1 G117.1(A) R132.2 R134.1
N$170: C101.1 R103.2
N$171: C111.2 R128.1
N$172: C103.1 C106.1 G107.2(K) R107.1 R109.1 R116.1 V110.E
N$173: C109.2 C113.2 G110.1(A) R131.2 R133.2
N$174: G105.2(K) V109.3(C)
N$175: R117.1 V110.C
N$176: R115.1 R116.2 V110.B
N$177: EIN1.1 R115.2 ; also sheet 4
N$178: G115.1(A) V114.3(C)
N$184: G120.2(K) G123.2(K) R139.1 R140.1 V116.2(B)
N$188: J106.2 R141.2 T1.14
N$189: R135.1 V117.3(E)
N$190: G124.1(A) R137.1 R138.1 T1.A2(1:A2) V119.1(E)
N$195: R111.2 V102.1(B)
N$196: R120.2 V103.1(B)
N$197: R126.2 V104.1(B)
N$198: R112.2 V101.1(B)
N$202: G112.2(K) R121.1
N$203: G102.1(A) R113.2
N$209: G122.2(K) R135.2 V116.1(C) V118.2(B)
N$211: G121.1(A) V117.2(B) ; also sheet 4
N$217: C105.1 G101.2(K) G107.1(A) R113.1 T101.3 T101.4 V101.3(E) V102.3(E)
N$222: C102.1 G104.1(A) G105.1(A) V108.3(C)
N$223: C112.2 G114.2(K) G115.2(K) V113.3(C)
OFFSET1: R234.1 ; also sheet 1

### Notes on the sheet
- UB0a
- MJE15030
- ein
- aus
- +39V
- -39V
- MJE15031
- +UB0a
- Schutzrelais
- Test
- 2-Wege Aktiv Box
- Netzgerät für
- Endstufe-Tiefton
- Juni 2009 | Wei | 4

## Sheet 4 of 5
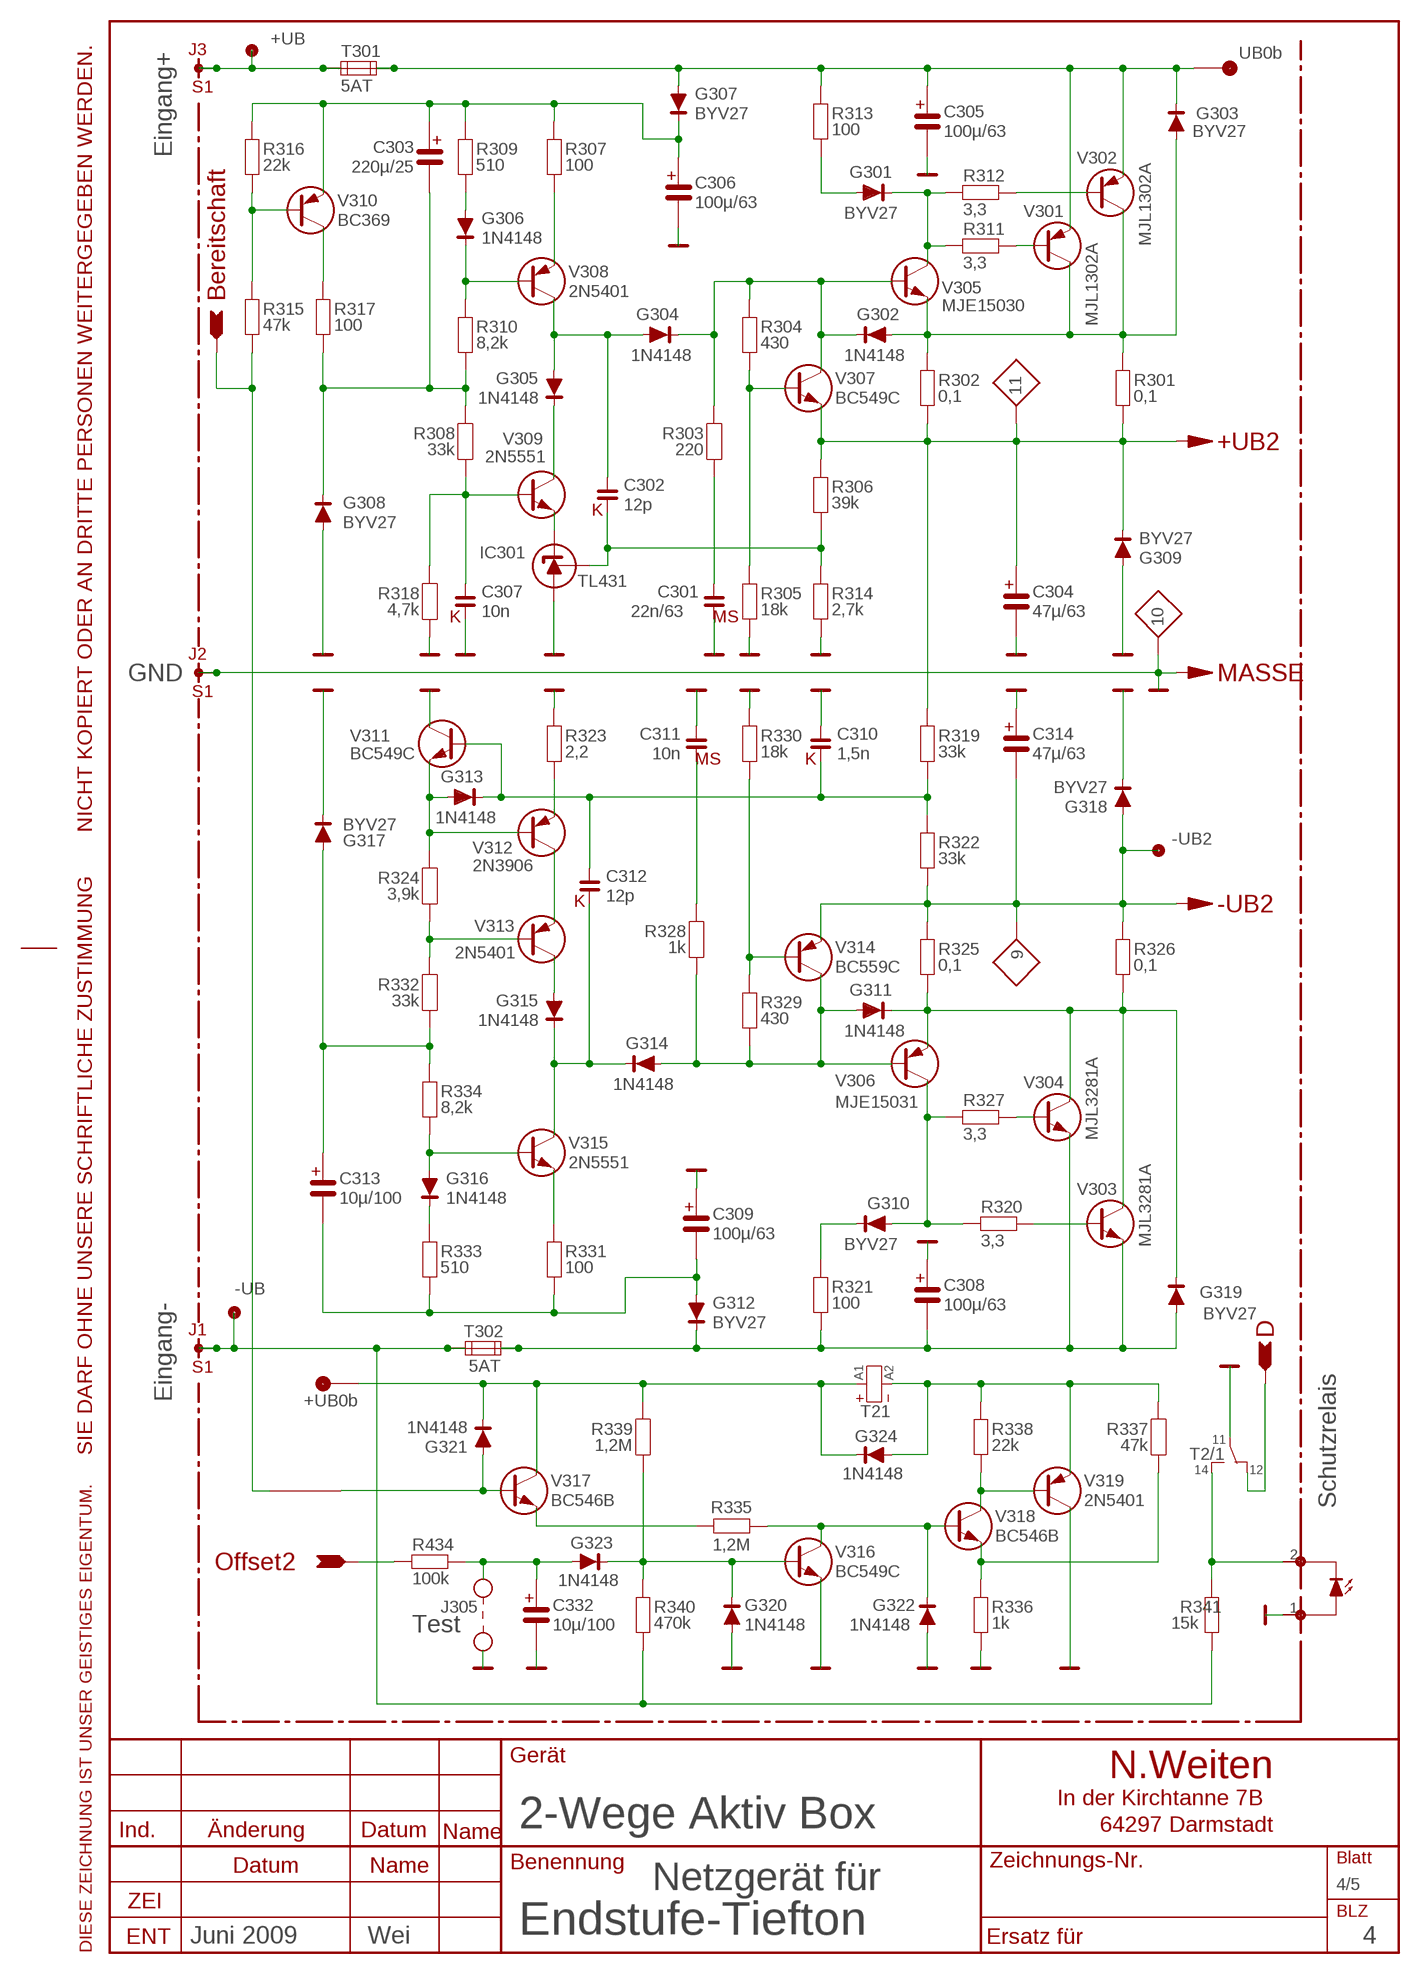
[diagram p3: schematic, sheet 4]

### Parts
C301  22n/63  M05S2,5/S  [M05T2,5]
C302  12p  K5S  [K5]
C303  220µ/25  E3,5S08/S  [E3,5S08]
C304  47µ/63  E3,5S08/S  [E3,5S08]
C305  100µ/63  E05S10/S  [E05S10,5]
C306  100µ/63  E05S10/S  [E05S10,5]
C307  10n  K5S  [K5]
C308  100µ/63  E05S10/S  [E05S10,5]
C309  100µ/63  E05S10/S  [E05S10,5]
C310  1,5n  K5S  [K5]
C311  10n  M05S2,5/S  [M05T2,5]
C312  12p  K5S  [K5]
C313  10µ/100  E2,0S05/S  [E2,0S05]
C314  47µ/63  E2,5S08/S  [E2,5S08]
C332  10µ/100  E2,0S05/S  [E2,0S05]
G301  BYV27  BYV27/L  [SOD-57]
G302  1N4148  1N4148/L  [DIO7-5]
G303  BYV27  BYV27/S  [SOD-57]
G304  1N4148  1N4148/L  [DIO7-5]
G305  1N4148  1N4148/S  [DIO7-5]
G306  1N4148  1N4148/S  [DIO7-5]
G307  BYV27  BYV27/S  [SOD-57]
G308  BYV27  BYV27/S  [SOD-57]
G309  BYV27  BYV27/S  [SOD-57]
G310  BYV27  BYV27/L  [SOD-57]
G311  1N4148  1N4148/L  [DIO7-5]
G312  BYV27  BYV27/S  [SOD-57]
G313  1N4148  1N4148/L  [DIO7-5]
G314  1N4148  1N4148/L  [DIO7-5]
G315  1N4148  1N4148/S  [DIO7-5]
G316  1N4148  1N4148/S  [DIO7-5]
G317  BYV27  BYV27/S  [SOD-57]
G318  BYV27  BYV27/S  [SOD-57]
G319  BYV27  BYV27/S  [SOD-57]
G320  1N4148  1N4148/S  [DIO7-5]
G321  1N4148  1N4148/S  [DIO7-5]
G322  1N4148  1N4148/S  [DIO7-5]
G323  1N4148  1N4148/S  [DIO7-5]
G324  1N4148  1N4148/S  [DIO7-5]
IC301  TL431  [TO-92/BC]
J1  FLACH6,3  [FLACH6,3]
J2  FLACH6,3  [FLACH6,3]
J3  FLACH6,3  [FLACH6,3]
J305  BERG02SG  JUMP/O/S  [BERG02SG]
J306  BERG02SW  [BERG02SW]
MP4  9  MESS-R/L  [MESSPU/R]
MP5  10  MESS-R/L  [MESSPU/R]
MP6  11  MESS-R/L  [MESSPU/R]
R301  0,1  R25X6,5/S  [R27,5]
R302  0,1  R25X6,5/S  [R27,5]
R303  220  R0204SR5  [R5]
R304  430  R0204SR5  [R5]
R305  18k  R0204SR5  [R5]
R306  39k  R0204SR5  [R5]
R307  100  R0204SR5  [R5]
R308  33k  R0204SR5  [R5]
R309  510  R0204SR5  [R5]
R310  8,2k  R0204SR5  [R5]
R311  3,3  R0207L7,5  [R7,5]
R312  3,3  R0207L7,5  [R7,5]
R313  100  R0207S7,5  [R7,5]
R314  2,7k  R0204SR5  [R5]
R315  47k  R0204SR5  [R5]
R316  22k  R0204SR5  [R5]
R317  100  R0204SR5  [R5]
R318  4,7k  R0204SR5  [R5]
R319  33k  R0207S7,5  [R7,5]
R320  3,3  R0207L7,5  [R7,5]
R321  100  R0207S7,5  [R7,5]
R322  33k  R0204SR5  [R5]
R323  2,2  R0204SR5  [R5]
R324  3,9k  R0204SR5  [R5]
R325  0,1  R25X6,5/S  [R27,5]
R326  0,1  R25X6,5/S  [R27,5]
R327  3,3  R0207L7,5  [R7,5]
R328  1k  R0204SR5  [R5]
R329  430  R0204SR5  [R5]
R330  18k  R0204SR5  [R5]
R331  100  R0204SR5  [R5]
R332  33k  R0204SR5  [R5]
R333  510  R0204SR5  [R5]
R334  8,2k  R0204SR5  [R5]
R335  1,2M  R0204LR5  [R5]
R336  1k  R0204SR5  [R5]
R337  47k  R0204SR5  [R5]
R338  22k  R0204SR5  [R5]
R339  1,2M  R0204SR5  [R5]
R340  470k  R0204SR5  [R5]
R341  15k  R0207S7,5  [R7,5]
R434  100k  R0204LR5  [R5]
T2  TYCORT314  [TYCORT314]
T301  5AT  SI520/L  [SICH5*20]
T302  5AT  SI520/L  [SICH5*20]
V301  MJL1302A  MJL1302ALU  [TO-264/LU]
V302  MJL1302A  MJL1302ALU  [TO-264/LU]
V303  MJL3281A  MJL3281ALU  [TO-264/LU]
V304  MJL3281A  MJL3281ALU  [TO-264/LU]
V305  MJE15028  MJE15030LU  [TO-220/LU]
V306  MJE15029  MJE15031LU  [TO-220/LU]
V307  BC549C  [TO-92/BC]
V308  2N5401  [TO-92]
V309  2N5551  [TO-92]
V310  BC369  BC640  [SOT-54]
V311  BC549C  [TO-92/BC]
V312  2N3906  [TO-92]
V313  2N5401  [TO-92]
V314  BC559C  [TO-92/BC]
V315  2N5551  [TO-92]
V316  BC549C  [TO-92/BC]
V317  BC546B  BC549C  [TO-92/BC]
V318  BC546B  BC549C  [TO-92/BC]
V319  2N5401  [TO-92]

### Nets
+UB: J3.1 J3.2 T301.1 T301.2 ; also sheet 3
+UB0: C305.1 G303.2(K) G307.1(A) R313.1 T301.3 T301.4 V301.3(E) V302.3(E)
+UB2: C304.1 G309.2(K) MP6.1 R301.2 R302.2 R306.1 R319.1 V307.3(E) ; also sheet 2
-UB: J1.1 J1.2 R340.2 R341.1 T302.1 T302.2 ; also sheet 3
-UB2: C314.2 G318.1(A) MP4.1 R322.2 R325.1 R326.1 V314.3(E) ; also sheet 2
MASSE: C301.2 C304.2 C305.2 C306.2 C307.2 C308.1 C309.1 C310.1 C311.1 C314.1 C332.2 G308.1(A) G309.1(A) G317.2(K) G318.2(K) G320.1(A) G322.1(A) IC301.2(A) J2.1 J2.2 J305.2 J306.1 MP5.1 R305.2 R314.2 R318.2 R323.1 R330.1 R336.2 T2.11 V311.1(C) V316.3(E) V319.3(C) ; also sheet 1,2,3
N$12: G306.2(K) R310.1 V308.2(B)
N$103: T2.12 ; also sheet 2
N$105: G301.1(A) R313.2
N$106: G306.1(A) R309.2
N$109: C303.2 G308.2(K) R308.1 R310.2 R317.2
N$110: C307.1 R308.2 R318.1 V309.2(B)
N$111: G302.2(K) G304.2(K) R303.1 R304.1 V305.1(B) V307.1(C)
N$112: IC301.3(K) V309.1(E)
N$113: G301.2(K) R311.1 R312.1 V305.2(C)
N$114: G302.1(A) G303.1(A) R301.1 R302.1 V301.2(C) V302.2(C) V305.3(E)
N$115: R304.2 R305.1 V307.2(B)
N$116: G321.2(K) G324.2(K) R339.1 T2.A1(1:A1) V317.1(C)
N$117: C302.2 IC301.1(R) R306.2 R314.1
N$118: C308.2 G312.2(K) G319.1(A) R321.2 T302.3 T302.4 V303.3(E) V304.3(E)
N$120: R323.2 V312.1(E)
N$121: G313.1(A) R324.1 V311.3(E) V312.2(B)
N$122: V312.3(C) V313.1(E)
N$123: R324.2 R332.1 V313.2(B)
N$124: C310.2 C312.1 G313.2(K) R319.2 R322.1 V311.2(B)
N$125: R329.1 R330.2 V314.2(B)
N$126: G311.1(A) G314.1(A) R328.2 R329.2 V306.1(B) V314.1(C)
N$127: G311.2(K) G319.2(K) R325.2 R326.2 V303.2(C) V304.2(C) V306.3(E)
N$128: G310.1(A) R320.1 R327.1 V306.2(C)
N$129: R331.1 V315.1(E)
N$130: G316.2(K) R333.1
N$131: G316.1(A) R334.2 V315.2(B)
N$132: C313.1 G317.1(A) R332.2 R334.1
N$133: C301.1 R303.2
N$134: C311.2 R328.1
N$135: C303.1 C306.1 G307.2(K) R307.1 R309.1 R316.1 V310.E
N$136: C309.2 C313.2 G312.1(A) R331.2 R333.2
N$137: G305.2(K) V309.3(C)
N$138: R317.1 V310.C
N$139: R315.1 R316.2 V310.B
N$141: G315.1(A) V313.3(C)
N$177: R315.2 ; also sheet 3
N$180: G324.1(A) R337.1 R338.1 T2.A2(1:A2) V319.1(E)
N$182: C332.1 G323.1(A) J305.1 R434.2
N$183: R335.2 V317.3(E)
N$186: J306.2 R341.2 T2.14
N$191: R312.2 V302.1(B)
N$192: R311.2 V301.1(B)
N$193: R320.2 V303.1(B)
N$194: R327.2 V304.1(B)
N$200: R336.1 R337.2 V318.3(E)
N$201: G310.2(K) R321.1
N$206: R338.2 V318.1(C) V319.2(B)
N$208: G322.2(K) R335.1 V316.1(C) V318.2(B)
N$210: G320.2(K) G323.2(K) R339.2 R340.1 V316.2(B)
N$211: G321.1(A) V317.2(B) ; also sheet 3
N$230: C302.1 G304.1(A) G305.1(A) V308.3(C)
N$231: C312.2 G314.2(K) G315.2(K) V315.3(C)
N$530: R307.2 V308.1(E)
OFFSET2: R434.1 ; also sheet 2

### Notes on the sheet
- UB0b
- Eingang+
- MJE15030
- GND
- MJE15031
- Eingang-
- +UB0b
- Schutzrelais
- Test
- 2-Wege Aktiv Box
- Netzgerät für
- Endstufe-Tiefton
- Juni 2009 | Wei | 4

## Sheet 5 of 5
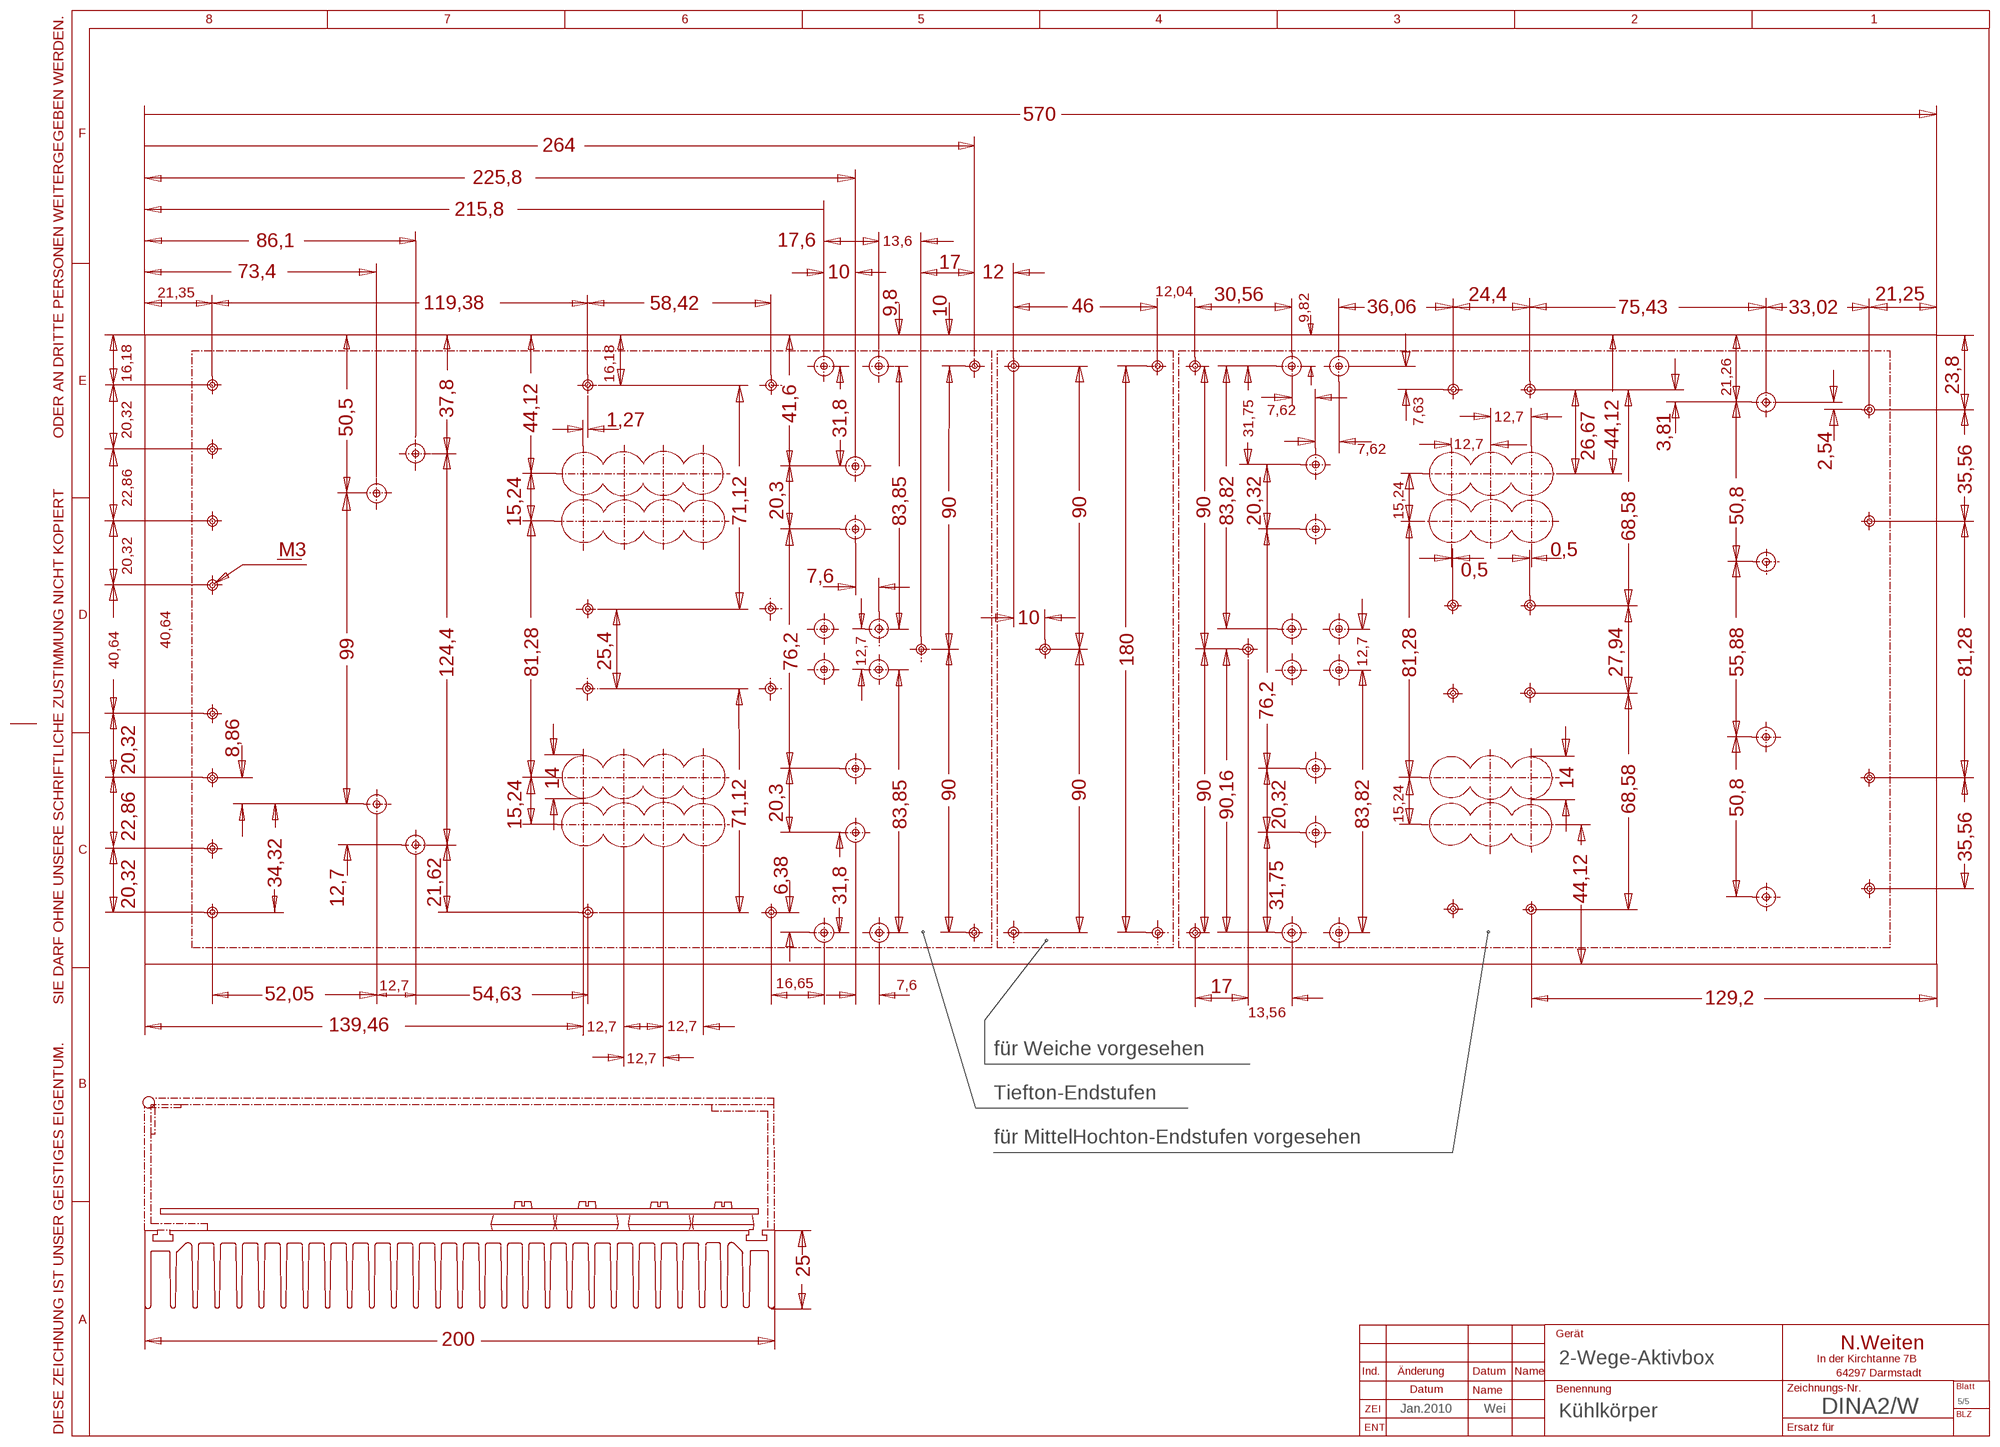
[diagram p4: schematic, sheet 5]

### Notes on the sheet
- 570
- 264
- 225,8
- 215,8
- 86,1 | 17,6 | 13,6
- 17
- 73,4 | 10 | 12
- 21,35 | 12,04
- 30,56 | 24,4 | 21,25
- 119,38 | 58,42 | 46 | 36,06 | 75,43 | 33,02
- 9,8 | 10
- 9,82
- 16,18 | 16,18
- 21,26 | 23,8
- 37,8 | 7,62
- 41,6 | 12,7
- 1,27 | 7,63
- 50,5 | 44,12
- 20,32 | 31,8 | 31,75
- 12,7 | 44,12 | 3,81
- 7,62
- 26,67
- 2,54
- 35,56
- 22,86
- 20,3 | 90 | 90 | 90 | 15,24
- 15,24 | 71,12 | 83,85 | 83,82 | 20,32 | 50,8
- 68,58
- M3 | 0,5
- 20,32 | 0,5
- 7,6
- 10
- 40,64
- 99
- 40,64 | 12,7 | 180 | 12,7
- 25,4 | 76,2
- 124,4 | 81,28 | 81,28 | 27,94 | 55,88 | 81,28
- 76,2
- 8,86
- 20,32
- 14 | 14
- 90 | 90 | 90
- 68,58 | 50,8
- 20,3 | 90,16 | 15,24
- 15,24 | 71,12 | 83,85 | 20,32 | 83,82
- 22,86
- 35,56
- 34,32
- 6,38
- 20,32 | 12,7 | 21,62 | 31,8 | 44,12
- 31,75
- 12,7 | 16,65 | 7,6
- 17
- 52,05 | 54,63 | 129,2
- 13,56
- 139,46 | 12,7 | 12,7
- für Weiche vorgesehen
- 12,7
- Tiefton-Endstufen
- für MittelHochton-Endstufen vorgesehen
- 25
- 200
- 2-Wege-Aktivbox
- Jan.2010 | Wei
- Kühlkörper

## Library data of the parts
C101 C111 C301 C311 = KOND:M05S2,5/S
C102 C107 C110 C112 C119 C124 C125 C302 C307 C310 C312 C319 C325 = KOND:K5S
C103 C104 C303 C304 = KOND:E3,5S08/S
C105 C106 C108 C109 C305 C306 C308 C309 = KOND:E05S10/S
C113 C132 C313 C332 = KOND:E2,0S05/S
C114 C314 = KOND:E2,5S08/S
C115-C118 C126-C129 C315-C318 C327-C330 = KOND:E05S12/L
C120 C320 = KOND:KP5/7/S
C121 C321 = KOND:M05S4,5/L
C122 C322 = KOND:M05C4,5/S
C130 C326 = KOND:M05C4,5/L
C131 C331 = KOND:M05S2,5/L
C324 = KOND:K5L
EIN1 = VERSCH35:LÖTFA
G101 G107-G110 G117-G119 G125 G126 G128-G133 G303 G307-G309 G312 G317-G319 G325-G328 G330-G333 = DIODEN:BYV27/S
G102 G112 G301 G310 = DIODEN:BYV27/L
G103 G111 G113 G114 G136 G137 G302 G304 G311 G313 G314 G336 G337 = DIODEN:1N4148/L
G104-G106 G115 G116 G120-G124 G135 G138 G139 G305 G306 G315 G316 G320-G324 G335 G338 G339 = DIODEN:1N4148/S
G127 G134 G329 G334 = DIODEN:BAT41
IC101 IC103 IC104 IC301 IC303 IC304 = ICS35:TL431
IC102 IC302 = ICS35:LM6361N
IC105 IC305 = ICS35:LF353
J1-J3 J101-J104 J301-J304 = STECKER:FLACH6,3
J4 J106 J306 = STECKER:BERG02SW
J105 J305 = STECKER:JUMP/O/S
J107 J307 = STECKER:SMBR665
MP1-MP3 MP7-MP12 MP15 MP16 = VERSCH35:MESS-R/S
MP4-MP6 MP13 MP14 = VERSCH35:MESS-R/L
P101 P301 = WID:POT6,7/S
R101 R102 R125 R127 R301 R302 R325 R326 = WID:R25X6,5/S
R103-R110 R114-R118 R122-R124 R128-R138 R140 R169 R171-R173 R175-R177 R180-R182 R185 R190 R193 R195-R201 R303-R310 R314-R318 R322-R324 R328-R334 R336-R340 R369 R371-R373 R375-R377 R380-R382 R385 R390 R393 R395-R401 = WID:R0204S
R111 R112 R120 R126 R142-R161 R183 R184 R203-R222 R311 R312 R320 R327 R342-R361 R383 R384 R403-R422 = WID:R0207L
R113 R119 R121 R141 R162 R164-R167 R174 R192 R223 R225-R228 R313 R319 R321 R341 R362 R364-R367 R374 R392 R423 R425-R428 = WID:R0207S
R139 R163 R168 R170 R186-R189 R191 R194 R202 R224 R229-R234 R335 R363 R368 R370 R386-R389 R391 R394 R402 R424 R429-R434 = WID:R0204L
R178 R179 R378 R379 = WID:NTC5,0/S
T1 T2 = RELAIS:TYCORT314
T101 T102 T301 T302 = VERSCH35:SI5*20/L
V101 V102 V120 V121 V301 V302 V320 V321 = TRANS:MJL1302A
V103 V104 V134 V135 V303 V304 V334 V335 = TRANS:MJL3281A
V105 V122 V137 V305 V322 V337 = TRANS:MJE15030
V106 V123 V136 V306 V323 V336 = TRANS:MJE15031
V107 V111 V116 V307 V311 V316-V318 = TRANS:BC549C
V108 V114 V119 V130 V308 V313 V319 V330 = TRANS:2N5401
V109 V113 V128 V309 V315 V328 = TRANS:2N5551
V110 V310 = TRANS:BC640
V112 V314 = TRANS:BC559C
V115 V312 = TRANS:2N3906
V117 V118 = TRANS:BC547C
V124 V127 V131 V324 V327 V331 = TRANS:BD140
V125 V129 V132 V325 V329 V332 = TRANS:BD139
V126 V326 = SMDREFLO:BCV62
V133 V333 = SMDREFLO:BCV61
